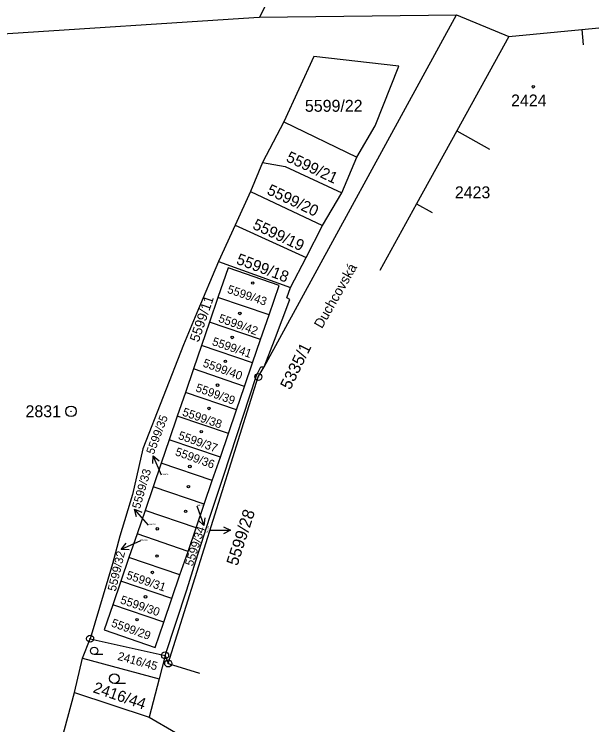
# Model space of a CAD drawing. Extents: x -825057 to -819383, y -1071633 to -1067888.
# Drawn here: x -820647.4 to -820564, y -1069468.9 to -1069367.7 of the extents above; entities that cross this region are included whole.
import ezdxf

# ---------------------------------------------------------------- set-up
doc = ezdxf.new("R2010")
doc.units = 0
for name, color, linetype in [('Vrstva 1', 7, 'Continuous'), ('Vrstva 15', 7, 'Continuous'), ('Vrstva 16', 7, 'Continuous'), ('Vrstva 17', 7, 'Continuous'), ('Vrstva 18', 7, 'Continuous'), ('Vrstva 19', 7, 'Continuous'), ('Vrstva 24', 7, 'Continuous'), ('Vrstva 25', 7, 'Continuous')]:
    doc.layers.add(name, color=color, linetype=linetype)

msp = doc.modelspace()

# ---------------------------------------------------------------- linework, layer by layer
at = {"layer": 'Vrstva 1'}
for p, q in [((-820609.28, -1069361.86), (-820612.45, -1069368.11)), ((-820652.78, -1069370.7), (-820613.24, -1069368.16)), ((-820613.24, -1069368.16), (-820612.45, -1069368.11)), ((-820612.45, -1069368.11), (-820584.32, -1069367.78)), ((-820611.78, -1069417.94), (-820584.32, -1069367.78)), ((-820584.32, -1069367.78), (-820576.86, -1069370.85)), ((-820576.86, -1069370.85), (-820566.48, -1069369.86)), ((-820566.48, -1069369.86), (-820564.04, -1069369.6)), ((-820566.48, -1069369.86), (-820566.26, -1069372.06)), ((-820576.86, -1069370.85), (-820584.28, -1069384.3)), ((-820604.7, -1069373.69), (-820608.97, -1069383.01)), ((-820592.57, -1069375.1), (-820604.7, -1069373.69)), ((-820595.93, -1069383.58), (-820592.57, -1069375.1)), ((-820608.97, -1069383.01), (-820612.02, -1069388.79)), ((-820608.97, -1069383.01), (-820598.54, -1069388.05)), ((-820598.54, -1069388.05), (-820595.93, -1069383.58)), ((-820584.28, -1069384.3), (-820590.03, -1069394.7)), ((-820584.28, -1069384.3), (-820579.65, -1069386.89)), ((-820600.7, -1069393.12), (-820598.54, -1069388.05)), ((-820612.02, -1069388.79), (-820613.73, -1069392.96)), ((-820612.02, -1069388.79), (-820608.78, -1069389.37)), ((-820608.78, -1069389.37), (-820600.7, -1069393.12)), ((-820613.73, -1069392.96), (-820615.88, -1069397.75)), ((-820613.73, -1069392.96), (-820603.45, -1069397.77)), ((-820603.45, -1069397.77), (-820600.7, -1069393.12)), ((-820590.03, -1069394.7), (-820595.27, -1069404.2)), ((-820590.03, -1069394.7), (-820587.81, -1069395.94)), ((-820615.88, -1069397.75), (-820618.28, -1069402.91)), ((-820615.88, -1069397.75), (-820605.78, -1069402.34)), ((-820605.78, -1069402.34), (-820603.45, -1069397.77)), ((-820607.99, -1069406.64), (-820605.78, -1069402.34)), ((-820618.28, -1069402.91), (-820621.36, -1069410.25)), ((-820618.28, -1069402.91), (-820607.99, -1069406.64)), ((-820616.92, -1069403.81), (-820618.37, -1069408.04)), ((-820609.63, -1069406.34), (-820616.92, -1069403.81)), ((-820611.06, -1069410.53), (-820609.63, -1069406.34)), ((-820608.54, -1069408.11), (-820607.99, -1069406.64)), ((-820618.37, -1069408.04), (-820619.57, -1069411.55)), ((-820611.06, -1069410.53), (-820618.37, -1069408.04)), ((-820610.29, -1069414.12), (-820608.08, -1069408.32)), ((-820608.08, -1069408.32), (-820608.54, -1069408.11)), ((-820621.36, -1069410.25), (-820623.26, -1069414.78)), ((-820612.27, -1069414.04), (-820611.06, -1069410.53)), ((-820619.57, -1069411.55), (-820620.7, -1069414.87)), ((-820612.27, -1069414.04), (-820619.57, -1069411.55)), ((-820623.26, -1069414.78), (-820629.07, -1069429.63)), ((-820613.41, -1069417.36), (-820612.27, -1069414.04)), ((-820611.78, -1069417.94), (-820610.29, -1069414.12)), ((-820620.7, -1069414.87), (-820621.85, -1069418.23)), ((-820613.41, -1069417.36), (-820620.7, -1069414.87)), ((-820614.56, -1069420.72), (-820613.41, -1069417.36)), ((-820621.85, -1069418.23), (-820623, -1069421.58)), ((-820614.56, -1069420.72), (-820621.85, -1069418.23)), ((-820612.85, -1069419.18), (-820612.25, -1069417.95)), ((-820612.6, -1069419.37), (-820611.78, -1069417.94)), ((-820612.25, -1069417.95), (-820611.78, -1069417.94)), ((-820625.45, -1069460.2), (-820612.6, -1069419.37)), ((-820617.58, -1069433.49), (-820612.85, -1069419.18)), ((-820615.71, -1069424.07), (-820614.56, -1069420.72)), ((-820623, -1069421.58), (-820624.15, -1069424.95)), ((-820615.71, -1069424.07), (-820623, -1069421.58)), ((-820624.15, -1069424.95), (-820625.29, -1069428.31)), ((-820616.86, -1069427.44), (-820624.15, -1069424.95)), ((-820616.86, -1069427.44), (-820615.71, -1069424.07)), ((-820618.01, -1069430.8), (-820616.86, -1069427.44)), ((-820625.29, -1069428.31), (-820626.43, -1069431.64)), ((-820618.01, -1069430.8), (-820625.29, -1069428.31)), ((-820629.07, -1069429.63), (-820630.55, -1069436.14)), ((-820619.16, -1069434.13), (-820618.01, -1069430.8)), ((-820626.43, -1069431.64), (-820627.59, -1069435.02)), ((-820619.16, -1069434.13), (-820626.43, -1069431.64)), ((-820619.49, -1069439.36), (-820617.58, -1069433.49)), ((-820627.59, -1069435.02), (-820628.73, -1069438.38)), ((-820620.32, -1069437.51), (-820627.59, -1069435.02)), ((-820620.32, -1069437.51), (-820619.16, -1069434.13)), ((-820630.55, -1069436.14), (-820632.33, -1069442.08)), ((-820621.47, -1069440.86), (-820620.32, -1069437.51)), ((-820628.73, -1069438.38), (-820629.89, -1069441.74)), ((-820621.47, -1069440.86), (-820628.73, -1069438.38)), ((-820621.52, -1069445.59), (-820619.49, -1069439.36)), ((-820622.62, -1069444.23), (-820621.47, -1069440.86)), ((-820632.33, -1069442.08), (-820633.38, -1069446.02)), ((-820629.89, -1069441.74), (-820631.04, -1069445.11)), ((-820622.62, -1069444.23), (-820629.89, -1069441.74)), ((-820631.04, -1069445.11), (-820632.19, -1069448.48)), ((-820623.78, -1069447.59), (-820631.04, -1069445.11)), ((-820623.78, -1069447.59), (-820622.62, -1069444.23)), ((-820633.38, -1069446.02), (-820636.58, -1069456.67)), ((-820622.79, -1069449.7), (-820621.52, -1069445.59)), ((-820624.93, -1069450.96), (-820623.78, -1069447.59)), ((-820632.19, -1069448.48), (-820633.33, -1069451.83)), ((-820624.93, -1069450.96), (-820632.19, -1069448.48)), ((-820625.89, -1069459.05), (-820622.79, -1069449.7)), ((-820626.08, -1069454.31), (-820624.93, -1069450.96)), ((-820633.33, -1069451.83), (-820634.56, -1069455.42)), ((-820626.08, -1069454.31), (-820633.33, -1069451.83)), ((-820627.31, -1069457.91), (-820626.08, -1069454.31)), ((-820634.56, -1069455.42), (-820627.31, -1069457.91)), ((-820637.66, -1069459.45), (-820636.58, -1069456.67)), ((-820636.58, -1069456.67), (-820625.89, -1069459.05)), ((-820625.89, -1069459.05), (-820626.73, -1069462.38)), ((-820625.89, -1069459.05), (-820625.45, -1069460.2)), ((-820638.8, -1069464.35), (-820637.66, -1069459.45)), ((-820637.66, -1069459.45), (-820626.73, -1069462.38)), ((-820625.45, -1069460.2), (-820620.98, -1069461.58)), ((-820626.73, -1069462.38), (-820628.16, -1069467.86)), ((-820641.46, -1069474.17), (-820638.8, -1069464.35)), ((-820638.8, -1069464.35), (-820628.16, -1069467.86)), ((-820628.16, -1069467.86), (-820624.39, -1069470.02))]:
    msp.add_line(p, q, dxfattribs=at)
at = {"layer": 'Vrstva 16'}
for p, q in [((-820626.41, -1069433.35), (-820627.575, -1069430.618)), ((-820626.41, -1069433.35), (-820627.575, -1069430.618)), ((-820621.36, -1069437.76), (-820620.358, -1069440.556)), ((-820621.36, -1069437.76), (-820620.358, -1069440.556)), ((-820628.26, -1069440.47), (-820630.26, -1069438.233)), ((-820628.26, -1069440.47), (-820630.26, -1069438.233)), ((-820619.56, -1069441.22), (-820616.56, -1069441.22)), ((-820619.56, -1069441.22), (-820616.56, -1069441.22)), ((-820629.39, -1069442.73), (-820632.135, -1069443.941)), ((-820629.39, -1069442.73), (-820632.135, -1069443.941))]:
    msp.add_line(p, q, dxfattribs=at)
for points in [[(-820627.642, -1069431.723), (-820627.575, -1069430.618), (-820626.731, -1069431.335)], [(-820627.642, -1069431.723), (-820627.575, -1069430.618), (-820626.731, -1069431.335)], [(-820629.966, -1069439.312), (-820630.26, -1069438.233), (-820629.22, -1069438.646)], [(-820629.966, -1069439.312), (-820630.26, -1069438.233), (-820629.22, -1069438.646)], [(-820620.226, -1069439.457), (-820620.358, -1069440.556), (-820621.158, -1069439.791)], [(-820620.226, -1069439.457), (-820620.358, -1069440.556), (-820621.158, -1069439.791)], [(-820617.56, -1069440.72), (-820616.56, -1069441.22), (-820617.56, -1069441.72)], [(-820617.56, -1069440.72), (-820616.56, -1069441.22), (-820617.56, -1069441.72)], [(-820631.018, -1069443.995), (-820632.135, -1069443.941), (-820631.422, -1069443.08)], [(-820631.018, -1069443.995), (-820632.135, -1069443.941), (-820631.422, -1069443.08)]]:
    msp.add_lwpolyline(points, dxfattribs=at)
at = {"layer": 'Vrstva 24'}
for centre, radius in [((-820612.6, -1069419.37), 0.5), ((-820612.6, -1069419.37), 0.5), ((-820612.6, -1069419.37), 0.0327), ((-820612.6, -1069419.37), 0.0327), ((-820639.31, -1069424.27), 0.75), ((-820639.31, -1069424.27), 0.75), ((-820639.31, -1069424.27), 0.0327), ((-820639.31, -1069424.27), 0.0327), ((-820636.58, -1069456.67), 0.5), ((-820636.58, -1069456.67), 0.5), ((-820636.58, -1069456.67), 0.0327), ((-820636.58, -1069456.67), 0.0327), ((-820625.89, -1069459.05), 0.5), ((-820625.89, -1069459.05), 0.5), ((-820625.89, -1069459.05), 0.0327), ((-820625.89, -1069459.05), 0.0327), ((-820625.45, -1069460.2), 0.5), ((-820625.45, -1069460.2), 0.5), ((-820625.45, -1069460.2), 0.0327), ((-820625.45, -1069460.2), 0.0327)]:
    msp.add_circle(centre, radius, dxfattribs=at)
at = {"layer": 'Vrstva 25'}
for p, q in [((-820634.775, -1069458.93), (-820636, -1069458.93)), ((-820634.775, -1069458.93), (-820636, -1069458.93)), ((-820631.555, -1069463.04), (-820633.13, -1069463.04)), ((-820631.555, -1069463.04), (-820633.13, -1069463.04))]:
    msp.add_line(p, q, dxfattribs=at)
for centre, radius in [((-820573.39, -1069378.02), 0.175), ((-820573.39, -1069378.02), 0.175), ((-820613.4, -1069405.99), 0.175), ((-820613.4, -1069405.99), 0.175), ((-820615.23, -1069410.32), 0.175), ((-820615.23, -1069410.32), 0.175), ((-820616.32, -1069413.74), 0.175), ((-820616.32, -1069413.74), 0.175), ((-820617.29, -1069417.13), 0.175), ((-820617.29, -1069417.13), 0.175), ((-820618.41, -1069420.54), 0.175), ((-820618.41, -1069420.54), 0.175), ((-820619.64, -1069423.86), 0.175), ((-820619.64, -1069423.86), 0.175), ((-820620.73, -1069427.18), 0.175), ((-820620.73, -1069427.18), 0.175), ((-820622.36, -1069432.13), 0.175), ((-820622.36, -1069432.13), 0.175), ((-820622.56, -1069435.01), 0.175), ((-820622.56, -1069435.01), 0.175), ((-820622.96, -1069438.52), 0.175), ((-820622.96, -1069438.52), 0.175), ((-820627, -1069441.01), 0.175), ((-820627, -1069441.01), 0.175), ((-820627.04, -1069444.89), 0.175), ((-820627.04, -1069444.89), 0.175), ((-820627.7, -1069447.23), 0.175), ((-820627.7, -1069447.23), 0.175), ((-820628.69, -1069450.71), 0.175), ((-820628.69, -1069450.71), 0.175), ((-820629.89, -1069453.97), 0.175), ((-820629.89, -1069453.97), 0.175), ((-820636, -1069458.405), 0.525), ((-820636, -1069458.405), 0.525), ((-820633.13, -1069462.365), 0.675), ((-820633.13, -1069462.365), 0.675)]:
    msp.add_circle(centre, radius, dxfattribs=at)

# ---------------------------------------------------------------- texts
at = {"layer": 'Vrstva 15'}
msp.add_text('Duchcovská', height=1.4, rotation=60.3, dxfattribs=at).set_placement((-820603.521, -1069412.569))
msp.add_text('Duchcovská', height=1.4, rotation=60.3, dxfattribs=at).set_placement((-820603.521, -1069412.569))
at = {"layer": 'Vrstva 16'}
for s, height, rotation, p in [('5599/35', 1.2, 69.3, (-820627.51, -1069430.5)), ('5599/35', 1.2, 69.3, (-820627.51, -1069430.5)), ('5599/33', 1.2, 73.8, (-820629.49, -1069438.25)), ('5599/33', 1.2, 73.8, (-820629.49, -1069438.25)), ('5599/28', 1.7, 72, (-820615.583, -1069446.395)), ('5599/28', 1.7, 72, (-820615.583, -1069446.395)), ('5599/34', 1.2, 72, (-820621.96, -1069446.42)), ('5599/34', 1.2, 72, (-820621.96, -1069446.42)), ('5599/32', 1.2, 76.5, (-820632.94, -1069449.99)), ('5599/32', 1.2, 76.5, (-820632.94, -1069449.99))]:
    msp.add_text(s, height=height, rotation=rotation, dxfattribs=at).set_placement(p)
at = {"layer": 'Vrstva 17'}
msp.add_text('2831', height=1.7, dxfattribs=at).set_placement((-820645.794, -1069425.11))
msp.add_text('2831', height=1.7, dxfattribs=at).set_placement((-820645.794, -1069425.11))
at = {"layer": 'Vrstva 18'}
msp.add_text('5599/22', height=1.7, dxfattribs=at).set_placement((-820605.948, -1069381.58))
msp.add_text('5599/22', height=1.7, dxfattribs=at).set_placement((-820605.948, -1069381.58))
for s, height, rotation, p in [('5599/21', 1.6, 334.8, (-820608.751, -1069388.581)), ('5599/21', 1.6, 334.8, (-820608.751, -1069388.581)), ('5599/20', 1.6, 334.8, (-820611.494, -1069393.266)), ('5599/20', 1.6, 334.8, (-820611.494, -1069393.266)), ('5599/19', 1.6, 334.8, (-820613.526, -1069398.192)), ('5599/19', 1.6, 334.8, (-820613.526, -1069398.192)), ('5599/18', 1.6, 339.3, (-820615.861, -1069403.204)), ('5599/18', 1.6, 339.3, (-820615.861, -1069403.204)), ('5599/11', 1.4, 71.1, (-820621.105, -1069414.493)), ('5599/11', 1.4, 71.1, (-820621.105, -1069414.493)), ('5335/1', 1.7, 63.9, (-820608.04, -1069421.31)), ('5335/1', 1.7, 63.9, (-820608.04, -1069421.31)), ('5599/28', 0.2, 72, (-820619.857, -1069441.592)), ('5599/28', 0.2, 72, (-820619.857, -1069441.592)), ('2416/45', 1.2, 344.7, (-820632.755, -1069459.672)), ('2416/45', 1.2, 344.7, (-820632.755, -1069459.672)), ('2416/44', 1.6, 341.1, (-820636.278, -1069464.282)), ('2416/44', 1.6, 341.1, (-820636.278, -1069464.282))]:
    msp.add_text(s, height=height, rotation=rotation, dxfattribs=at).set_placement(p)
at = {"layer": 'Vrstva 19'}
for s, height, p in [('2424', 1.7, (-820576.552, -1069380.82)), ('2424', 1.7, (-820576.552, -1069380.82)), ('2423', 1.7, (-820584.569, -1069393.91)), ('2423', 1.7, (-820584.569, -1069393.91)), ('5599/35', 0.2, (-820626.41, -1069433.35)), ('5599/35', 0.2, (-820626.41, -1069433.35)), ('5599/34', 0.2, (-820621.36, -1069437.76)), ('5599/34', 0.2, (-820621.36, -1069437.76)), ('5599/33', 0.2, (-820628.26, -1069440.47)), ('5599/33', 0.2, (-820628.26, -1069440.47)), ('5599/32', 0.2, (-820629.39, -1069442.73)), ('5599/32', 0.2, (-820629.39, -1069442.73))]:
    msp.add_text(s, height=height, dxfattribs=at).set_placement(p)
for s, rotation, p in [('5599/43', 341.1, (-820617.12, -1069407.36)), ('5599/43', 341.1, (-820617.12, -1069407.36)), ('5599/42', 340.2, (-820618.38, -1069411.48)), ('5599/42', 340.2, (-820618.38, -1069411.48)), ('5599/41', 341.1, (-820619.28, -1069414.8)), ('5599/41', 341.1, (-820619.28, -1069414.8)), ('5599/40', 340.2, (-820620.6, -1069417.86)), ('5599/40', 340.2, (-820620.6, -1069417.86)), ('5599/39', 340.2, (-820621.63, -1069421.38)), ('5599/39', 340.2, (-820621.63, -1069421.38)), ('5599/38', 341.1, (-820623.52, -1069424.85)), ('5599/38', 341.1, (-820623.52, -1069424.85)), ('5599/37', 340.2, (-820624.12, -1069428.17)), ('5599/37', 340.2, (-820624.12, -1069428.17)), ('5599/36', 340.2, (-820624.55, -1069430.5)), ('5599/36', 340.2, (-820624.55, -1069430.5)), ('5599/31', 341.1, (-820631.52, -1069448.09)), ('5599/31', 341.1, (-820631.52, -1069448.09)), ('5599/30', 341.1, (-820632.38, -1069451.61)), ('5599/30', 341.1, (-820632.38, -1069451.61)), ('5599/29', 340.2, (-820633.67, -1069454.9)), ('5599/29', 340.2, (-820633.67, -1069454.9))]:
    msp.add_text(s, height=1.2, rotation=rotation, dxfattribs=at).set_placement(p)

doc.saveas('drawing.dxf')
